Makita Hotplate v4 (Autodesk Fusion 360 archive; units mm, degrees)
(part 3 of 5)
sketch "Plan" plane through (0, 0, 0) normal (0, 0, 1) x axis (1, 0, 0)
  line L1 (-35, -5) -> (35, -5)
  line L2 (-35, 5) -> (-35, -5)
  line L3 (35, 5) -> (-35, 5)
  line L4 (35, -5) -> (35, 5)
  line L5 (-32.4254, -7.4282) -> (-37.6216, -10.4282)
  line L6 (-40.4254, 6.4282) -> (-32.4254, -7.4282)
  line L7 (-45.6216, 3.4282) -> (-40.4254, 6.4282)
  line L8 (-37.6216, -10.4282) -> (-45.6216, 3.4282)
  line L9 (-35.0235, -8.9282) -> (-43.0235, 4.9282)
  line L10 (-35, -3.8) -> (-35.5, -3.8)
  line L11 (-35, 3.8) -> (-35.5, 3.8)
  line L12 (-35.5, -3.8) -> (-35.5, 3.8)
  line L13 (-35.5, 0) -> (-35, 0)
  line L14 (0, -5) -> (0, 5)
  line L15 (35, 0) -> (-35, 0)
  line L16 (-30.35, 3) -> (-35, 3)
  line L17 (-30.35, -5) -> (-30.35, 3)
  line L18 (-58.5, 1.7343) -> (-50.3233, -12.4282)
  line L19 (-58.5, 20.45) -> (-58.5, 1.7343)
  line L20 (-35.1895, 7.2) -> (0, 7.2)
  line L21 (-33.6575, -9.2942) -> (-41.1827, 3.7398)
  line L22 (35, 20.45) -> (0, 20.45)
  line L23 (35, 7.2) -> (0, 7.2)
  line L24 (-58.5, 20.45) -> (0, 20.45)
  line L25 (0, 20.45) -> (0, 7.2)
  line L26 (-35.1895, 7.2) -> (-41.1827, 3.7398)
  line L27 (-35, 7.2) -> (-35.1895, 7.2)
  line L28 (-35, 20.45) -> (-35, 7.2)
  line L29 (35, 20.45) -> (35, 7.2)
  line L30 (-39.0857, -12.4282) -> (-33.6575, -9.2942)
  line L31 (-50.3233, -12.4282) -> (-39.0857, -12.4282)
  line L32 (40.7735, -5) -> (35, 5)
  line L33 (7.5981, -1.5) -> (5, 0)
  line L34 (49, 20.45) -> (35, 20.45)
  arc A1 centre (-32.1029, 0) radius 5.0971 clockwise from (-35.5, -3.8) to (-35.5, 3.8)
  circle C1 centre (-33.25, 0) radius 3
  circle C2 centre (5, 0) radius 3
  circle C3 centre (-33.35, 0) radius 3
  point P10 (-43.0235, 4.9282)
  point P11 (-35.0235, -8.9282)
  point P15 (-35, -3.8)
  point P16 (-35, 3.8)
  point P14 (-35.5, -3.8)
  point P17 (-35.5, -3.8)
  point P18 (-35, 0)
  point P19 (-35.5, 0)
  point P20 (-37.2, 0)
  point P21 (0, 5)
  point P22 (0, -5)
  point P1 (0, 0)
  point P24 (35, 0)
  point P23 (-33.25, 0)
  point P25 (-35, 3)
  point P27 (-30.35, -5)
  point P28 (-39.0235, -2)
  point P33 (0, 7.2)
  point P36 (0, 7.2)
  point P30 (-58.5, 20.45)
  point P38 (-58.5, 20.45)
  point P31 (-35.1895, 7.2)
  point P39 (-35.1895, 7.2)
  point P41 (-35, 20.45)
  point P4 (-35, 5)
  point P42 (35, 7.2)
  point P5 (35, 5)
  point P37 (35, 7.2)
  point P47 (40.7735, -5)
  point P48 (41.1575, -5.6651)
  point P35 (5, 0)
  point P49 (5, 0)
  point P50 (7.5981, -1.5)
  point P51 (7.5981, -1.5)
  point P53 (-33.35, 0)
  point P3 (-35, -5)
  point P6 (-37.6216, -10.4282)
  point P9 (-45.6216, 3.4282)
  point P8 (-40.4254, 6.4282)
  point P13 (-35.5, 3.8)
  point P34 (0, 20.45)
  point P43 (35, 20.45)
  point P52 (49, 20.45)
  horizontal L1
  vertical L2
  horizontal L3
  vertical L4
  perpendicular L5 L6
  parallel L5 L7
  parallel L6 L8
  midpoint L7 P10
  midpoint L5 P11
  coincident L2 P15
  perpendicular L2 L10
  coincident L2 P16
  perpendicular L2 L11
  perpendicular L11 L12
  coincident P14 P17
  midpoint L2 P18
  perpendicular L2 L13
  midpoint L12 P19
  midpoint A1 P20
  midpoint L3 P21
  midpoint L1 P22
  midpoint P1 L14
  midpoint L4 P24
  coincident P23 L15
  coincident L2 P25
  perpendicular L2 L16
  coincident L1 P27
  perpendicular L1 L17
  midpoint L9 P28
  vertical L19
  horizontal L20
  coincident P33 P36
  coincident P30 P38
  perpendicular L22 L25
  coincident P1 L25
  horizontal L22
  horizontal L23
  horizontal L24
  perpendicular L6 L26
  coincident P31 P39
  parallel L9 L21
  parallel L9 L18
  parallel L20 L27
  coincident L24 P41
  perpendicular L24 L28
  coincident P4 L28
  coincident L23 P42
  perpendicular L22 L29
  coincident P5 L29
  tangent L6 C1
  perpendicular L21 L30
  coincident P37 P42
  coincident L1 P47
  horizontal L31
  parallel L9 L32
  coincident L32 P48
  coincident P35 P49
  coincident C2 P50
  coincident P50 P51
  equal C1 C2
  coincident L15 P35
  perpendicular L29 L34
  coincident L15 P53
  equal C1 C3
  dimension "d1706" distance P3 P4 = 10
  dimension "d1707" distance P6 P9 = 16
  dimension "d1708" distance P8 P9 = 6
  dimension "d1709" distance P13 P17 = 7.6
  dimension "d1710" distance L2 P20 = 2.2
  dimension "d1711" distance P13 P16 = 0.5
  dimension "d1712" distance P1 L2 = 35
  dimension "d1713" diameter C1 = 6
  dimension "d1714" distance L2 P23 = 1.75
  dimension "d1715" distance P23 L17 = 2.9 (= "d1713 / 2 - d2773")
  dimension "d1716" distance P23 L16 = 3 (= "d1713 / 2")
  dimension "d1717" angle L2 L9 = 30
  dimension "d1723" distance L15 P28 = 2
  dimension "d1734" distance P28 L21 = 1
  dimension "d1740" distance L2 L19 = 23.5
  dimension "d1955" distance L15 L20 = 7.2
  dimension "d1988" distance P33 P34 = 13.25
  dimension "d1989" distance P4 L26 = 2
  dimension "d1990" distance P28 L18 = 15
  dimension "d2127" distance L3 L20 = 2.2
  dimension "d2158" distance L19 L28 = 23.5
  dimension "d2277" distance P6 L30 = 1
  dimension "d2278" distance P6 L31 = 2
  dimension "d2412" angle L15 L33 = 30
  dimension "d2460" distance P35 L29 = 30 (= "right_int_offset")
  dimension "d2467" distance P43 P52 = 14
  dimension "d2773" distance P23 P53 = 0.1
  dimension "d523" OffsetX = 0
  dimension "d524" OffsetY = 0
  dimension "d525" OffsetZ = 0
  dimension "d526" AngleZ = 0
  dimension "d567" OffsetX = 0
  dimension "d568" OffsetY = 0
  dimension "d569" OffsetZ = 0
  dimension "d570" AngleZ = 0
  dimension "d2536" distance = 15.5
  dimension "d2537" radius = 29.5
  dimension "d2538" radius = 29
  dimension "d2539" distance = 8
  dimension "d2540" distance = 12
  dimension "d2542" distance = 30
  dimension "d2543" radius = 45
  dimension "d2544" Side1Offset = 0.5
  dimension "d2545" TaperAngle = 0
  dimension "d2546" Side1Offset = 0
  dimension "d2547" TaperAngle = 0
  dimension "d2548" AlongDistance = -8
  dimension "d2549" TaperAngle = 0
  dimension "d2550" Side1Offset = 0
  dimension "d2551" TaperAngle = 0
  dimension "d2552" angle = 8
  dimension "d2553" distance = 39
  dimension "d2554" Side1Offset = 0
  dimension "d2555" TaperAngle = 0
  dimension "d2556" distance = 0.5
  dimension "d2558" Radius = 4
  dimension "d2560" Radius = 3
  dimension "d2562" Radius = 5
  dimension "d2564" Radius = 2
  dimension "d2566" Radius = 12
  dimension "d2568" Radius = 2
  dimension "d2569" Distance = 2
  dimension "d2570" Distance = 2
  dimension "d2571" Distance = 4
  dimension "d2573" Side1Offset = 0
  dimension "d2574" TaperAngle = 0
  dimension "d2575" Side1Offset = 0
  dimension "d2576" TaperAngle = 0
  dimension "d2577" distance = -0.25
  dimension "d2579" Radius = 6
  dimension "d2581" ChordLen = 1
  dimension "d2583" ChordLen = 1
  dimension "d2585" ChordLen = 1
  dimension "d2587" ChordLen = 1
  dimension "d2588" distance = 12
  dimension "d2589" diameter = 6
  dimension "d2590" diameter = 3.25
  dimension "d2591" distance = 5.5
  dimension "d2592" angle = 90
  dimension "d2593" distance = 5.4
  dimension "d2594" Side1Offset = 0
  dimension "d2595" TaperAngle = 0
  dimension "d2596" AlongDistance = -4.5
  dimension "d2597" TaperAngle = 0
  dimension "d2598" Distance = 0.5
  dimension "d2599" Distance = 1.5
  dimension "d2600" distance = 25
  dimension "d2602" TotalAngle = 360
  dimension "d2603" distance = 5.5
  dimension "d2604" diameter = 6
  dimension "d2605" diameter = 3.25
  dimension "d2607" distance = 3.75
  dimension "d2608" distance = 1.5
  dimension "d2609" Side1Offset = 0
  dimension "d2610" TaperAngle = 0
  dimension "d2611" AlongDistance = -4.5
  dimension "d2612" TaperAngle = 0
  dimension "d2613" Distance = 0.5
  dimension "d2614" Distance = 1.5
  dimension "d2615" countU = 11
  dimension "d2616" TotalAngle = 360
  dimension "d1941" Side1Offset = 0
  dimension "d1942" TaperAngle = 0
  dimension "d1943" Side1Offset = 0
  dimension "d1944" TaperAngle = 0
  dimension "d1947" alignAngle = 0
  dimension "d1948" alignOffsetX = 0
  dimension "d1949" alignOffsetY = 0
  dimension "d1950" alignOffsetZ = 0
  dimension "d1951" alignAngle = 90
  dimension "d1952" alignOffsetX = 0
  dimension "d1953" alignOffsetY = 0
  dimension "d1954" alignOffsetZ = 0
  dimension "d1958" ProfileOffset = 0
  dimension "d1959" Side1Offset = 0
  dimension "d1960" TaperAngle = 0
  dimension "d1961" distance = -0.075
  dimension "d1962" ProfileOffset = 0
  dimension "d1963" Side1Offset = 0
  dimension "d1964" TaperAngle = 0
  dimension "d1965" distance = -0.075
  dimension "d1966" distance = 67
  dimension "d1967" distance = 33
  dimension "d1968" diameter = 2.5
  dimension "d1969" distance = 4
  dimension "d1970" distance = 29
  dimension "d1971" distance = 34
  dimension "d1972" distance = 54
  dimension "d1973" distance = 4
  dimension "d1974" distance = 3
  dimension "d1975" distance = 3
  dimension "d1976" distance = 5
  dimension "d1977" distance = 5
  dimension "d1978" distance = 1
  dimension "d1979" distance = 1
  dimension "d1980" distance = 10
  dimension "d1981" distance = 10
  dimension "d1982" distance = 6
  dimension "d1983" ProfileOffset = 0
  dimension "d1984" Side1Offset = 0
  dimension "d1985" TaperAngle = 0
  dimension "d1987" Radius = 1.05 (= "od_mintool / 2")
  dimension "d1597" distance = 1.6
  dimension "d1598" distance = 67
  dimension "d1599" diameter = 4.25
  dimension "d1600" diameter = 3.3
  dimension "d1601" distance = 1
  dimension "d1602" distance = 1
  dimension "d1603" distance = 0.5
  dimension "d1604" distance = 12
  dimension "d1605" distance = 0.25
  dimension "d1606" distance = 0.25
  dimension "d1607" distance = 1
  dimension "d1608" distance = 8
  dimension "d1609" distance = 4.5
  dimension "d1610" distance = 4.5
  dimension "d1612" TaperAngle = 0
  dimension "d1613" AlongDistance = -53 (= "-20 mm - 33 mm")
  dimension "d1614" TaperAngle = 0
  dimension "d1615" ProfileOffset = 0.1
  dimension "d1616" Side1Offset = 0
  dimension "d1617" TaperAngle = 0
  dimension "d1618" leftDistance = 1
  dimension "d1619" distance = 67
  dimension "d1620" distance = 33
  dimension "d1621" distance = 0.5
  dimension "d1622" distance = 24.5
  dimension "d1623" diameter = 2.5
  dimension "d1624" distance = 4
  dimension "d1625" distance = 34
  dimension "d1626" distance = 54
  dimension "d1627" distance = 4
  dimension "d1628" distance = 29
  dimension "d1631" distance = 1
  dimension "d1633" distance = 3
  dimension "d1634" distance = 2.44 (= "d1643")
  dimension "d1635" diameter = 4
  dimension "d1636" distance = 15
  dimension "d1637" distance = 3
  dimension "d1638" distance = 15
  dimension "d1639" distance = 2
  dimension "d1640" Side1Offset = 0
  dimension "d1641" TaperAngle = 0
  dimension "d1642" distance = 2.44
  dimension "d1643" distance = 2.44
  dimension "d1644" AlongDistance = -16
  dimension "d1645" TaperAngle = 0
  dimension "d1647" Radius = 1
  dimension "d1649" Radius = 1
  dimension "d1651" Radius = 5
  dimension "d1653" Radius = 1
  dimension "d1654" diameter = 12
  dimension "d1655" Side1Offset = 0
  dimension "d1656" TaperAngle = 0
  dimension "d1658" Radius = 2
  dimension "d1659" distance = 20
  dimension "d1660" distance = 5
  dimension "d1661" distance = 5
  dimension "d981" distance = 15 (= "( 30 / 2 ) * 1 mm")
  dimension "d982" distance = 8
  dimension "d983" distance = 1.5
  dimension "d984" distance = 0.3
  dimension "d985" distance = 4
  dimension "d987" distance = 1
  dimension "d988" distance = 7.5
  dimension "d989" distance = 5
  dimension "d990" distance = 0.5
  dimension "d991" AlongAngle = 60
  dimension "d992" AgainstAngle = 60
  dimension "d993" distance = 4
  dimension "d994" angle = 60
  dimension "d995" angle = 60 (= "d994")
  dimension "d1004" diameter = 6.5
  dimension "d1005" distance = 1.5
  dimension "d1006" AlongDistance = -10
  dimension "d1007" TaperAngle = 0
  dimension "d1008" Side1Offset = 0
  dimension "d1009" TaperAngle = 0
  dimension "d1010" ProfileOffset = 0
  dimension "d1011" AlongDistance = -0.5
  dimension "d1012" TaperAngle = 0
  dimension "d1013" AlongDistance = 2.5
  dimension "d1014" TaperAngle = 0
  dimension "d1015" leftDistance = 0.25
  dimension "d1017" Radius = 1
  dimension "d1019" TotalAngle = 360
  dimension "d1020" ProfileOffset = 0
  dimension "d1021" Side1Offset = 0
  dimension "d1022" TaperAngle = 0
  dimension "d1028" angle = 25
  dimension "d1029" ProfileOffset = 0
  dimension "d1030" Side1Offset = 0
  dimension "d1031" TaperAngle = 0
  dimension "d1032" ProfileOffset = 0
  dimension "d1034" TaperAngle = 0
  dimension "d1035" Side1Offset = 0
  dimension "d1036" distance = 3
  dimension "d1037" leftDistance = 3
  dimension "d1038" rightDistance = 17.25
  dimension "d1039" Side1Offset = 0
  dimension "d1040" TaperAngle = 0
  dimension "d1042" TotalAngle = 360
  dimension "d1043" Side1Offset = 0
  dimension "d1044" TaperAngle = 2
  dimension "d1045" angle = 1
  dimension "d1047" Side1Offset = 0
  dimension "d1048" TaperAngle = 0
  dimension "d1049" distance = -1 (= "0 mm - 1 mm")
  dimension "d1051" TotalAngle = 360
  dimension "d1053" angle = 43.731
  dimension "d1054" angle = 28 (= "d1055 - d1056")
  dimension "d1055" angle = 50 (= "d1028 * 2")
  dimension "d1056" angle = 22
  dimension "d1058" Radius = 2
  dimension "d1060" Radius = 2
  dimension "d1061" alignAngle = 0
  dimension "d1062" alignOffsetX = 0
  dimension "d1063" alignOffsetY = 0
  dimension "d1064" alignOffsetZ = 0
  dimension "d1082" distance = 0.8
  dimension "d1084" distance = 0.8
  dimension "d1085" distance = 1.2
  dimension "d1086" distance = 1.2
  dimension "d1087" distance = 0.1
  dimension "d1093" Radius = 0.5
  dimension "d1095" Radius = 0.5
  dimension "d1097" Radius = 2
  dimension "d1103" distance = 1.3
  dimension "d1105" TotalAngle = 360
  dimension "d1106" distance = 2.75 (= "hw_m3hex_d / 2")
  dimension "d1107" distance = 1.75 (= "hw_m3_thru / 2")
  dimension "d1108" angle = 45
  dimension "d1109" distance = 3.6
  dimension "d1110" distance = 20
  dimension "d1111" distance = 1.7
  dimension "d1112" AlongAngle = 360
  dimension "d1113" Side1Offset = 0
  dimension "d1114" TaperAngle = 0
  dimension "d1116" TotalAngle = 360
  dimension "d1118" Radius = 2
  dimension "d1120" distance = 3.175 (= "1 / 8 * 1")
  dimension "d1121" radius = 12
  dimension "d1123" radius = 6.5
  dimension "d1124" angle = 60
  dimension "d1126" distance = 2.8797 (= "13 / 64 * 1  / 2 + 0.3 mm")
  dimension "d1127" distance = 9.5563 (= "7 / 32 * 1  + 4 mm")
  dimension "d1128" AlongDistance = -6
  dimension "d1129" diameter = 3.475 (= "1 / 8 * 1  + 0.3 mm")
  dimension "d1130" diameter = 1.7875 (= "1 / 16 * 1  + 0.2 mm")
  dimension "d1141" TwistAngle = 0
  dimension "d1142" TaperAngle = 0
  dimension "d1143" angle = 51
  dimension "d1144" distance = 2.8797 (= "d1126")
  dimension "d1145" diameter = 1.7875 (= "1 / 16 * 1  + 0.2 mm")
  dimension "d1150" TwistAngle = 0
  dimension "d1151" TaperAngle = 0
  dimension "d1152" distance = 1.7875 (= "1 / 16 * 1  + 0.2 mm")
  dimension "d1153" Side1Offset = 0
  dimension "d1154" TaperAngle = 0
  dimension "d1155" AlongDistance = -4
  dimension "d1156" TaperAngle = 0
  dimension "d1157" diameter = 5.3594 (= "13 / 64 * 1  + 0.2 mm")
  dimension "d1158" AlongDistance = 1.5
  dimension "d1159" TaperAngle = 0
  dimension "d1164" TwistAngle = 0
  dimension "d1165" TaperAngle = 0
  dimension "d1167" mirrorStitchTolerance = 0.1
  dimension "d1169" Radius = 0.4
  dimension "d1170" distance = 11
  dimension "d1171" distance = 1.0938 (= "( 1 / 16 * 1  + 0.2 mm ) / 2 + 0.2 mm")
  dimension "d1172" distance = 1.7
  dimension "d1173" distance = 1.7
  dimension "d1174" Side1Offset = 0
  dimension "d1175" TaperAngle = 0
  dimension "d1176" Side2Offset = -1
  dimension "d1177" Side2TaperAngle = 0
  dimension "d1179" mirrorStitchTolerance = 0.1
  dimension "d1181" Radius = 0.5
  dimension "d1182" alignAngle = 0
  dimension "d1183" alignOffsetX = 0
  dimension "d1184" alignOffsetY = 0
  dimension "d1185" alignOffsetZ = 0
  dimension "d1186" leftDistance = 0.75
  dimension "d1187" rightDistance = 3
  dimension "d1189" Radius = 12
  dimension "d1191" Radius = 2
  dimension "d1193" Radius = 0.5
  dimension "d1195" Radius = 0.5
  dimension "d1197" Radius = 0.5
  dimension "d1198" alignAngle = 0
  dimension "d1199" alignOffsetX = 0
  dimension "d1200" alignOffsetY = 0
  dimension "d1201" alignOffsetZ = 0
  dimension "d1202" distance = 13.5
sketch "Elevation" plane through (0, 0, 0) normal (0, 1, 0) x axis (1, 0, 0)
  line L1 (35, 0) -> (-35, 0)
  line L2 (35, -120) -> (35, 0)
  line L3 (-35, -120) -> (35, -120)
  line L4 (-35, 0) -> (-35, -120)
  line L5 (-35, 0) -> (35, 0)
  line L6 (25, -108) -> (-25, -108)
  line L7 (25, -12) -> (25, -108)
  line L8 (-25, -12) -> (25, -12)
  line L9 (-25, -108) -> (-25, -12)
  line L10 (-38, -80.5) -> (-58.5, -80.5)
  line L11 (-38, -39.5) -> (-38, -80.5)
  line L12 (-58.5, -39.5) -> (-38, -39.5)
  line L13 (-43.25, -84.75) -> (-53.25, -84.75)
  line L14 (-43.25, -35.25) -> (-43.25, -84.75)
  line L15 (-53.25, -35.25) -> (-43.25, -35.25)
  line L16 (-53.25, -84.75) -> (-53.25, -35.25)
  line L17 (-48.25, -60) -> (-48.25, -84.75)
  line L18 (-38, -60) -> (-48.25, -60)
  line L19 (-58.5, -90) -> (-58.5, -80.5)
  line L20 (-35, -90) -> (-58.5, -90)
  line L21 (-58.5, -30) -> (-35, -30)
  line L22 (-58.5, -39.5) -> (-58.5, -30)
  line L23 (-50.0746, -84.75) -> (-51.6623, -87.5)
  line L24 (-51.6623, -82) -> (-50.0746, -84.75)
  line L25 (-54.8377, -82) -> (-51.6623, -82)
  line L26 (-56.4254, -84.75) -> (-54.8377, -82)
  line L27 (-54.8377, -87.5) -> (-56.4254, -84.75)
  line L28 (-51.6623, -87.5) -> (-54.8377, -87.5)
  line L29 (-46.4254, -84.75) -> (-44.8377, -82)
  line L30 (-44.8377, -87.5) -> (-46.4254, -84.75)
  line L31 (-41.6623, -87.5) -> (-44.8377, -87.5)
  line L32 (-40.0746, -84.75) -> (-41.6623, -87.5)
  line L33 (-41.6623, -82) -> (-40.0746, -84.75)
  line L34 (-44.8377, -82) -> (-41.6623, -82)
  line L35 (-40.0746, -35.25) -> (-41.6623, -32.5)
  line L36 (-41.6623, -38) -> (-40.0746, -35.25)
  line L37 (-44.8377, -38) -> (-41.6623, -38)
  line L38 (-46.4254, -35.25) -> (-44.8377, -38)
  line L39 (-41.6623, -32.5) -> (-44.8377, -32.5)
  line L40 (-44.8377, -32.5) -> (-46.4254, -35.25)
  line L41 (-54.8377, -38) -> (-51.6623, -38)
  line L42 (-56.4254, -35.25) -> (-54.8377, -38)
  line L43 (-54.8377, -32.5) -> (-56.4254, -35.25)
  line L44 (-51.6623, -32.5) -> (-54.8377, -32.5)
  line L45 (-51.6623, -38) -> (-50.0746, -35.25)
  line L46 (-50.0746, -35.25) -> (-51.6623, -32.5)
  line L47 (-49.25, -85.75) -> (-49.25, -80.5)
  line L48 (-47.25, -80.5) -> (-47.25, -85.75)
  line L49 (-48.25, -85.75) -> (-48.25, -80.5)
  line L50 (-49.25, -34.25) -> (-49.25, -39.5)
  line L51 (-47.25, -39.5) -> (-47.25, -34.25)
  line L52 (-38, -90) -> (-38, -80.5)
  line L53 (-38, -30) -> (-38, -39.5)
  line L54 (35, -54) -> (-35, -54)
  line L55 (0, 0) -> (0, -120)
  line L56 (25, -64.25) -> (35, -64.25)
  line L57 (25, -43.75) -> (35, -43.75)
  line L58 (25, -28.75) -> (35, -28.75)
  line L59 (25, -79.25) -> (35, -79.25)
  line L60 (30, -64.25) -> (30, -43.75)
  line L61 (5, -120) -> (5, 0)
  line L62 (2.2, -39) -> (2.2, -68)
  line L63 (8.2, -63) -> (2.2, -63)
  line L64 (8.2, -68) -> (8.2, -63)
  line L65 (8.2, -39) -> (8.2, -63)
  line L66 (9.25, -20) -> (0.75, -20)
  line L67 (9.25, -37) -> (9.25, -20)
  line L68 (0.75, -37) -> (9.25, -37)
  line L69 (0.75, -20) -> (0.75, -37)
  line L70 (-30.35, -97) -> (-35, -97)
  line L71 (-30.35, -120) -> (-30.35, -97)
  line L72 (-30.35, -97) -> (-30.35, 0)
  line L73 (-35, -114) -> (-30.35, -114)
  line L74 (8.2, -46) -> (2.2, -46)
  line L75 (-37.35, -114) -> (-35, -114)
  line L76 (-37.35, -120) -> (-37.35, -114)
  line L77 (-35, -120) -> (-37.35, -120)
  line L78 (5.5, -46) -> (5.5, -63)
  line L79 (-15, -7.55) -> (-35, -7.55)
  line L80 (-15, -16.45) -> (-35, -16.45)
  line L81 (45, -120) -> (35, -120)
  line L82 (45, 0) -> (45, -120)
  line L83 (35, 0) -> (45, 0)
  line L84 (-27.5, -96.75) -> (-35, -96.75)
  line L85 (-27.5, -23.25) -> (-27.5, -96.75)
  line L86 (-35, -23.25) -> (-27.5, -23.25)
  line L87 (2.2, -68) -> (20, -68)
  line L88 (20, -39) -> (2.2, -39)
  line L89 (20, -39) -> (20, -68)
  line L90 (-36.6, -23.25) -> (-35, -23.25)
  line L91 (-36.6, 0) -> (-36.6, -23.25)
  line L92 (-35, 0) -> (-36.6, 0)
  circle C1 centre (-53.25, -84.75) radius 1.625
  circle C2 centre (-43.25, -84.75) radius 1.625
  circle C3 centre (-43.25, -35.25) radius 1.625
  circle C4 centre (-53.25, -35.25) radius 1.625
  arc A1 centre (-48.25, -85.75) radius 1 clockwise from (-47.25, -85.75) to (-49.25, -85.75)
  arc A2 centre (-48.25, -80.5) radius 1 clockwise from (-49.25, -80.5) to (-47.25, -80.5)
  arc A3 centre (-48.25, -34.25) radius 1 clockwise from (-49.25, -34.25) to (-47.25, -34.25)
  arc A4 centre (-48.25, -39.5) radius 1 clockwise from (-47.25, -39.5) to (-49.25, -39.5)
  circle C5 centre (-29, -12) radius 1.65
  circle C6 centre (-29, -12) radius 4
  circle C7 centre (-25, -108) radius 1.65
  circle C8 centre (-25, -108) radius 4
  circle C9 centre (40.5, -54) radius 1.65
  circle C10 centre (40.5, -54) radius 4
  circle C11 centre (20, -53.5) radius 13.3
  arc A5 centre (20, -53.5) radius 14.5 clockwise from (20, -39) to (20, -68)
  point P2 (-35, 0)
  point P4 (-35, 0)
  point P3 (35, 0)
  point P1 (0, 0)
  point P15 (0, 0)
  point P24 (-48.25, -84.75)
  point P27 (-43.25, -60)
  point P26 (-38, -60)
  point P28 (-48.25, -80.5)
  point P30 (-35, -90)
  point P19 (-58.5, -39.5)
  point P32 (-58.5, -39.5)
  point P20 (-53.25, -84.75)
  point P33 (-53.25, -84.75)
  point P21 (-43.25, -84.75)
  point P34 (-43.25, -84.75)
  point P41 (-53.25, -84.75)
  point P48 (-43.25, -84.75)
  point P35 (-51.6623, -87.5)
  point P60 (-51.6623, -32.5)
  point P36 (-50.0746, -84.75)
  point P61 (-50.0746, -35.25)
  point P37 (-51.6623, -82)
  point P56 (-51.6623, -38)
  point P38 (-54.8377, -82)
  point P57 (-54.8377, -38)
  point P39 (-56.4254, -84.75)
  point P58 (-56.4254, -35.25)
  point P40 (-54.8377, -87.5)
  point P59 (-54.8377, -32.5)
  point P42 (-44.8377, -82)
  point P53 (-44.8377, -38)
  point P43 (-46.4254, -84.75)
  point P54 (-46.4254, -35.25)
  point P44 (-44.8377, -87.5)
  point P55 (-44.8377, -32.5)
  point P45 (-41.6623, -87.5)
  point P50 (-41.6623, -32.5)
  point P46 (-40.0746, -84.75)
  point P51 (-40.0746, -35.25)
  point P47 (-41.6623, -82)
  point P52 (-41.6623, -38)
  point P68 (-48.25, -85.75)
  point P67 (-48.25, -80.5)
  point P63 (-49.25, -80.5)
  point P69 (-49.25, -39.5)
  point P64 (-49.25, -85.75)
  point P70 (-49.25, -34.25)
  point P65 (-47.25, -85.75)
  point P72 (-47.25, -34.25)
  point P66 (-47.25, -80.5)
  point P73 (-47.25, -39.5)
  point P75 (-38, -90)
  point P76 (-38, -30)
  point P77 (-35, -54)
  point P78 (35, -54)
  point P8 (-35, -30)
  point P79 (0, -120)
  point P80 (0, 0)
  point P81 (0, -108)
  point P83 (-58.5, 0)
  point P84 (35, -64.25)
  point P85 (25, -64.25)
  point P86 (35, -43.75)
  point P87 (25, -43.75)
  point P88 (35, -28.75)
  point P89 (25, -28.75)
  point P90 (35, -79.25)
  point P91 (25, -79.25)
  point P92 (30, -43.75)
  point P93 (30, -64.25)
  point P94 (30, -54)
  point P95 (5, 0)
  point P96 (5, 0)
  point P97 (5, -120)
  point P100 (2, -54)
  point P101 (2.2, -63)
  point P104 (8.2, -39)
  point P109 (5, -20)
  point P110 (-35, -97)
  point P112 (-30.35, -120)
  point P113 (-30.35, 0)
  point P114 (-30.35, 0)
  point P115 (-30.35, -114)
  point P116 (-35, -114)
  point P117 (2.2, -46)
  point P118 (8.2, -46)
  point P7 (-35, -120)
  point P121 (-35, -120)
  point P122 (5.5, -63)
  point P123 (5.5, -46)
  point P126 (-35, -7.55)
  point P128 (-35, -16.45)
  point P124 (-29, -12)
  point P130 (-25, -108)
  point P134 (5, -54)
  point P5 (35, 0)
  point P137 (35, 0)
  point P138 (-35, -96.75)
  point P141 (-35, -23.25)
  point P142 (-27.5, -60)
  point P143 (20, -53.5)
  point P144 (20, -53.5)
  point P103 (8.2, -68)
  point P132 (40.5, -54)
  point P149 (-35, 0)
  point P6 (35, -120)
  point P16 (-58.5, -80.5)
  point P17 (-38, -80.5)
  point P18 (-38, -39.5)
  point P23 (-53.25, -35.25)
  point P11 (-25, -108)
  point P12 (25, -108)
  point P13 (25, -12)
  point P102 (8.2, -63)
  point P105 (0.75, -20)
  point P106 (9.25, -20)
  point P108 (0.75, -37)
  point P111 (-30.35, -97)
  point P119 (-37.35, -114)
  point P14 (-25, -12)
  point P127 (-15, -7.55)
  point P125 (-29, -12)
  point P131 (-25, -108)
  point P135 (45, -120)
  point P133 (40.5, -54)
  point P140 (-27.5, -23.25)
  point P139 (-27.5, -96.75)
  point P148 (-36.6, 0)
  horizontal L1
  vertical L2
  horizontal L3
  vertical L4
  coincident P2 P4
  coincident P3 L2
  horizontal L6
  vertical L7
  horizontal L8
  vertical L9
  coincident P1 P15
  horizontal L10
  perpendicular L10 L11
  perpendicular L11 L12
  horizontal L13
  vertical L14
  horizontal L15
  vertical L16
  midpoint L13 P24
  perpendicular L10 L17
  perpendicular L17 L18
  midpoint L14 P27
  coincident L18 P27
  midpoint L11 P26
  midpoint L10 P28
  coincident L17 P28
  perpendicular L10 L19
  coincident L4 P30
  perpendicular L4 L20
  perpendicular L4 L21
  perpendicular L21 L22
  coincident P19 P32
  coincident L19 P32
  equal L19 L22
  coincident P20 P33
  coincident P21 P34
  equal C1 C2
  coincident P33 P41
  horizontal L28
  coincident P34 P48
  horizontal L31
  equal L28 L31
  symmetric L18 C1 C4
  symmetric L18 C2 C3
  symmetric L18 P35 P60
  symmetric L18 P36 P61
  symmetric L18 P37 P56
  symmetric L18 P38 P57
  symmetric L18 P39 P58
  symmetric L18 P40 P59
  symmetric L18 P42 P53
  symmetric L18 P43 P54
  symmetric L18 P44 P55
  symmetric L18 P45 P50
  symmetric L18 P46 P51
  symmetric L18 P47 P52
  tangent L47 A1
  tangent A1 L48
  parallel L47 L48
  tangent L48 A2
  tangent L47 A2
  coincident L17 P68
  perpendicular L10 L49
  coincident P28 P67
  symmetric L18 P63 P69
  symmetric L18 P64 P70
  symmetric L18 P65 P72
  symmetric L18 P66 P73
  symmetric L18 A1 A3
  symmetric L18 A2 A4
  coincident L20 P75
  perpendicular L20 L52
  coincident L21 P76
  perpendicular L21 L53
  coincident L4 P77
  coincident L2 P78
  perpendicular L2 L54
  coincident L4 P8
  midpoint L3 P79
  coincident P1 P80
  midpoint L6 P81
  coincident L55 P81
  coincident L19 P83
  coincident L2 P84
  coincident L7 P85
  perpendicular L7 L56
  coincident L2 P86
  coincident L7 P87
  perpendicular L7 L57
  coincident L2 P88
  coincident L7 P89
  perpendicular L7 L58
  coincident L2 P90
  coincident L7 P91
  perpendicular L7 L59
  midpoint L57 P92
  midpoint L56 P93
  midpoint L60 P94
  coincident L54 P94
  coincident P95 P96
  coincident L3 P97
  perpendicular L3 L61
  perpendicular L54 L62
  perpendicular L2 L88
  coincident L54 P100
  coincident L62 P101
  perpendicular L62 L63
  coincident P104 L88
  perpendicular L65 L88
  horizontal L66
  vertical L67
  horizontal L68
  vertical L69
  midpoint L66 P109
  coincident L61 P109
  coincident L4 P110
  perpendicular L4 L70
  coincident L3 P112
  perpendicular L3 L71
  coincident P113 P114
  vertical L72
  coincident L71 P115
  coincident L4 P116
  perpendicular L4 L73
  coincident L62 P117
  coincident L65 P118
  perpendicular L65 L74
  perpendicular L4 L75
  perpendicular L73 L76
  perpendicular L4 L77
  coincident P7 P121
  coincident L63 P122
  coincident L74 P123
  perpendicular L74 L78
  concentric C5 C6
  coincident L4 P126
  perpendicular L4 L79
  coincident L4 P128
  perpendicular L9 L80
  equal L79 L80
  coincident L8 P124
  concentric C7 C8
  coincident L6 P130
  concentric C9 C10
  coincident L61 P134
  coincident L54 P134
  perpendicular L2 L81
  perpendicular L3 L82
  perpendicular L2 L83
  coincident P5 P137
  coincident L4 P138
  perpendicular L72 L84
  perpendicular L84 L85
  coincident L4 P141
  perpendicular L4 L86
  midpoint L85 P142
  coincident P143 P144
  perpendicular L88 L89
  coincident P144 L89
  coincident P103 L87
  vertical L64
  horizontal L87
  coincident L54 P132
  perpendicular L4 L90
  perpendicular L90 L91
  perpendicular L91 L92
  coincident P4 P149
  dimension "d1741" distance P5 P6 = 120
  dimension "d2014" distance P16 P17 = 20.5
  dimension "d2015" distance P17 P18 = 41
  dimension "d2016" distance P20 P23 = 49.5
  dimension "d2017" distance P20 P21 = 10
  dimension "d2019" diameter C1 = 3.25
  dimension "d2020" distance P38 L28 = 5.5
  dimension "d2021" distance P64 L48 = 2
  dimension "d2204" distance L13 P68 = 1
  dimension "d2269" distance P4 L18 = 60
  dimension "d2271" distance P11 P12 = 50
  dimension "d2272" distance P12 P13 = 96
  dimension "d2273" distance P1 L8 = 12
  dimension "d2274" distance L3 L6 = 12 (= "d2273")
  dimension "d2275" distance P6 P7 = 70
  dimension "d2279" distance L20 P40 = 2.5
  dimension "d2295" distance P88 P90 = 50.5
  dimension "d2296" distance P84 P86 = 20.5
  dimension "d2297" distance L59 P93 = 15
  dimension "d2298" distance L58 P92 = 15 (= "d2297")
  dimension "d2336" distance P13 L54 = 42
  dimension "d2337" distance L6 L54 = 54
  dimension "d2618" distance L61 L62 = 2.8
  dimension "d2619" distance P101 P102 = 6
  dimension "d2620" distance P100 L63 = 9
  dimension "d2622" distance P105 P106 = 8.5
  dimension "d2623" distance P105 P108 = 17
  dimension "d2625" distance P112 L73 = 6
  dimension "d2626" distance P111 L73 = 17
  dimension "d2641" distance P100 L74 = 8
  dimension "d2643" distance P115 P119 = 7
  dimension "d2675" distance L61 L78 = 0.5
  dimension "d2676" diameter C5 = 3.3
  dimension "d2677" diameter C6 = 8
  dimension "d2678" distance P14 L79 = 4.45 (= "( 8.9 / 2 ) * 1 mm")
  dimension "d2679" distance P14 L80 = 4.45 (= "d2678")
  dimension "d2680" distance P126 P127 = 20
  dimension "d2681" distance L4 P125 = 6
  dimension "d2682" diameter C7 = 3.3
  dimension "d2683" diameter C8 = 8
  dimension "d2684" distance L4 P131 = 10
  dimension "d2693" diameter C9 = 3.3
  dimension "d2694" diameter C10 = 8
  dimension "d2695" distance P108 P117 = 9
  dimension "d2713" distance P6 P135 = 10
  dimension "d2714" distance P133 L82 = 4.5
  dimension "d2718" distance P140 P141 = 7.5
  dimension "d2719" distance P139 P140 = 73.5
  dimension "d2720" distance L1 P142 = 60
  dimension "d2757" distance L55 P143 = 20
  dimension "d2759" diameter C11 = 26.6
  dimension "d2760" radius A5 = 14.5 (= "( 29 / 2 ) * 1 mm")
  dimension "d2761" distance L54 P143 = 0.5
  dimension "d2772" distance P148 P149 = 1.6
  dimension "d1938" diameter = 4.25
  dimension "d1940" diameter = 8
  dimension "d1945" distance = 25
  dimension "d1946" distance = 30
  dimension "d1956" distance = 5 (= "t_sheet_THIN")
  dimension "d1957" distance = 5.5 (= "d1748")
extrude "Extrude245" sketch "Elevation" profile of L1 L2 L3 L4 L5 L87 L62 L88 L63 L64 L65 L66 L67 L68 L69 L70 L71 L73 L74 L75 L76 L77 L78 C5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 to an object
extrude "Extrude246" sketch "Elevation" profile of L4 L62 L63 L65 L70 L71 L73 L74 L78 to an object
fillet "Fillet116" ChordLen 3
sketch "Center Dowel Thru" plane through (0, 0, 63) normal (0, 0, -1) x axis (1, 0, 0)
  line L1 (5.5, -3) -> (5.2, -3)
  line L2 (8.2, 5) -> (8.2, -5)
  line L3 (2.2, 5) -> (8.2, 5)
  line L4 (2.2, 0) -> (2.2, 5)
  line L5 (5.2, 0) -> (2.2, 0)
  line L6 (5.2, -3) -> (5.2, 0)
  line L7 (5.5, -5) -> (5.5, -3)
  line L8 (8.2, -5) -> (5.5, -5)
  circle C1 centre (5.2, 0) radius 2.125
  arc A1 centre (5.2, 0) radius 3 clockwise from (5.2, -3) to (2.2, 0)
  circle C2 centre (5.2, 0) radius 1.75
  point P2 (2.2, 0)
  point P8 (2.2, 0)
  point P3 (5.2, -3)
  point P10 (5.2, -3)
  point P7 (5.2, 0)
  point P9 (5.2, 0)
  coincident P2 P8
  perpendicular L4 L5
  perpendicular L5 L6
  coincident P3 P10
  coincident P7 P9
  concentric A1 C2
  dimension "d2635" diameter C1 = 4.25
  dimension "d2638" diameter C2 = 3.5
extrude "Extrude247" cut sketch "Center Dowel Thru" profile of C1 C2 to an object
sketch "Upper Left Dowel Thru" plane through (0, 0, 114) normal (0, 0, -1) x axis (1, 0, 0)
  line L1 (-30.35, 5) -> (-30.35, 0)
  line L2 (-37.35, 5) -> (-30.35, 5)
  line L3 (-35, -3) -> (-35, -5)
  line L4 (-33.35, -3) -> (-35, -3)
  line L5 (-37.35, -5) -> (-37.35, 5)
  line L6 (-35, -5) -> (-37.35, -5)
  arc A1 centre (-33.35, 0) radius 3 clockwise from (-30.35, 0) to (-33.35, -3)
  circle C1 centre (-33.35, 0) radius 2.125
  concentric A1 C1
  dimension "d2642" diameter C1 = 4.25
extrude "Extrude249" cut sketch "Upper Left Dowel Thru" profile of C1 to an object
chamfer "Chamfer38" distance 0.5
sketch "Lower Left Contacts" plane through (-36.6, 0, 0) normal (-1, 0, 0) x axis (0, -1, 0)
  line L1 (-3, 97) -> (5, 97)
  line L2 (-3, 114) -> (-3, 97)
  line L3 (-5, 114) -> (-3, 114)
  line L4 (-5, 96.75) -> (-5, 114)
  line L5 (5, 97) -> (5, 96.75)
  line L6 (0, 6.2) -> (0, 17.8)
  line L7 (-2.5, 12) -> (5, 16.3301)
  line L8 (5, 7.6699) -> (-2.5, 12)
  line L9 (-2.5, 12) -> (0, 12)
  line L10 (5, 96.75) -> (-5, 96.75)
  line L11 (5, 96.75) -> (5, 97)
  line L12 (-5, 0) -> (-5, 23.25)
  line L13 (5, 0) -> (-5, 0)
  line L14 (5, 23.25) -> (5, 0)
  line L15 (-5, 23.25) -> (5, 23.25)
  line L16 (5, 12) -> (3.125, 15.2476)
  line L17 (-2.5, 12) -> (5, 12)
  circle C1 centre (0, 17.8) radius 1.8
  circle C2 centre (0, 6.2) radius 1.8
  circle C3 centre (0, 17.8) radius 4
  point P9 (0, 17.8)
  point P11 (0, 17.8)
  point P10 (0, 6.2)
  point P12 (0, 6.2)
  point P8 (0, 12)
  point P13 (5, 16.3301)
  point P15 (5, 7.6699)
  point P16 (0, 12)
  point P25 (5, 12)
  point P24 (3.125, 15.2476)
  coincident P9 P11
  coincident P10 P12
  vertical L6
  midpoint P8 L6
  equal C1 C2
  coincident L5 P13
  coincident L5 P15
  coincident P8 P16
  horizontal L9
  concentric C1 C3
  coincident L14 P25
  horizontal L17
  coincident L7 P24
  perpendicular L7 L16
  dimension "d2647" distance P11 P12 = 11.6
  dimension "d2648" diameter C1 = 3.6
  dimension "d2649" angle L7 L8 = 60 (= "d2650 * 2")
  dimension "d2650" angle L7 L9 = 30
  dimension "d2774" diameter C3 = 8
  dimension "d2777" distance P24 P25 = 3.75
extrude "Extrude250" cut sketch "Lower Left Contacts" profile of C1 C2 against normal blind 20
extrude "Extrude251" cut sketch "Lower Left Contacts" profile of L7 L8 L14 against normal blind 5
chamfer "Chamfer39" distance 5 distance 3.75
chamfer "Chamfer41" distance 3
fillet "Fillet117" ChordLen 4
chamfer "Chamfer42" distance 1
sketch "PCB Mount" plane through (-27.5, 0, 0) normal (-1, 0, 0) x axis (0, -1, 0)
  line L1 (-5, 23.25) -> (-5, 96.75)
  line L2 (5, 23.25) -> (-5, 23.25)
  line L3 (5, 96.75) -> (5, 23.25)
  line L4 (-5, 96.75) -> (5, 96.75)
  line L5 (3, 43.55) -> (3, 76.45)
  line L6 (5, 60) -> (3, 60)
  line L7 (3, 27.5) -> (3, 43.55)
  line L8 (3, 92.5) -> (3, 76.45)
  line L9 (41.3, 96.75) -> (5, 96.75)
  line L10 (41.3, 23.25) -> (41.3, 96.75)
  line L11 (5, 23.25) -> (41.3, 23.25)
  line L12 (-0.7, 96.75) -> (-0.7, 23.25)
  line L13 (37.3, 82.5) -> (37.3, 37.5)
  line L14 (37.3, 27.5) -> (3, 27.5)
  line L15 (37.3, 92.5) -> (3, 92.5)
  line L16 (6, 73.95) -> (-0.7, 73.95)
  line L17 (6, 46.05) -> (6, 73.95)
  line L18 (-0.7, 46.05) -> (6, 46.05)
  line L19 (31.8, 94.5) -> (18.3, 94.5)
  line L20 (31.8, 89.5) -> (31.8, 94.5)
  line L21 (18.3, 89.5) -> (31.8, 89.5)
  line L22 (18.3, 94.5) -> (18.3, 89.5)
  circle C1 centre (3, 76.45) radius 0.85
  circle C2 centre (3, 43.55) radius 0.85
  circle C3 centre (3, 92.5) radius 1.75
  circle C4 centre (3, 27.5) radius 1.75
  circle C5 centre (37.3, 82.5) radius 1.75
  circle C6 centre (37.3, 37.5) radius 1.75
  point P6 (3, 76.45)
  point P8 (3, 76.45)
  point P7 (3, 43.55)
  point P9 (3, 43.55)
  point P10 (3, 60)
  point P11 (5, 60)
  point P12 (3, 43.55)
  point P14 (3, 76.45)
  point P15 (3, 92.5)
  point P16 (3, 92.5)
  point P13 (3, 27.5)
  point P17 (3, 27.5)
  point P5 (5, 96.75)
  point P18 (5, 96.75)
  point P4 (5, 23.25)
  point P21 (5, 23.25)
  point P22 (-0.7, 23.25)
  point P23 (-0.7, 96.75)
  point P25 (37.3, 37.5)
  point P26 (37.3, 37.5)
  point P24 (37.3, 82.5)
  point P27 (37.3, 82.5)
  point P28 (3, 27.5)
  point P29 (37.3, 27.5)
  point P30 (3, 92.5)
  point P31 (37.3, 92.5)
  point P32 (-0.7, 73.95)
  point P35 (-0.7, 46.05)
  point P19 (41.3, 96.75)
  point P38 (31.8, 89.5)
  point P39 (18.3, 89.5)
  coincident P6 P8
  coincident P7 P9
  vertical L5
  midpoint L5 P10
  midpoint L3 P11
  horizontal L6
  equal C1 C2
  coincident P7 P12
  parallel L5 L7
  coincident P6 P14
  parallel L5 L8
  equal L7 L8
  coincident P15 P16
  coincident P13 P17
  equal C3 C4
  coincident P5 P18
  perpendicular L3 L9
  perpendicular L4 L10
  perpendicular L10 L11
  coincident P4 P21
  coincident L2 P22
  coincident L4 P23
  perpendicular L4 L12
  coincident P25 P26
  coincident P24 P27
  vertical L13
  equal C5 C6
  equal C3 C5
  coincident P17 P28
  horizontal L14
  coincident L13 P29
  coincident P16 P30
  perpendicular L8 L15
  coincident L13 P31
  coincident L12 P32
  perpendicular L12 L16
  perpendicular L16 L17
  coincident L12 P35
  perpendicular L12 L18
  horizontal L19
  vertical L20
  horizontal L21
  vertical L22
  dimension "d2729" distance P6 P7 = 32.9
  dimension "d2730" distance L1 P10 = 8
  dimension "d2731" diameter C1 = 1.7
  dimension "d2732" distance P13 P15 = 65
  dimension "d2733" diameter C3 = 3.5
  dimension "d2742" distance L5 L12 = 3.7
  dimension "d2764" distance P19 L12 = 42
  dimension "d2765" distance L10 L13 = 4
  dimension "d2766" distance L11 P25 = 14.25
  dimension "d2768" distance P26 P27 = 45
  dimension "d2769" distance P25 P29 = 10 (= "d2770")
  dimension "d2770" distance P24 P31 = 10
  dimension "d2779" distance P7 L18 = 2.5
  dimension "d2780" distance P6 L16 = 2.5
  dimension "d2781" distance P6 L17 = 3
  dimension "d2782" distance P31 L19 = 2
  dimension "d2783" distance P31 L21 = 3
  dimension "d2784" distance P38 P39 = 13.5
  dimension "d2785" distance P31 L20 = 5.5
extrude "Extrude255" add sketch "PCB Mount" profile of L3 C1 C2 C3 C4 L9 L10 L11 C5 C6 against normal blind 8
extrude "Extrude256" cut sketch "PCB Mount" profile of L3 C1 C2 C3 C4 against normal blind 9
extrude "Extrude259" cut sketch "PCB Mount" profile of L19 L20 L21 L22 against normal blind 3
extrude "Extrude257" add sketch "PCB Mount" profile of L2 L3 L4 C1 C2 C3 C4 L9 L10 L11 L12 C5 C6 L16 L17 L18 L19 L20 L21 L22 along normal blind 0.5
chamfer "Chamfer43" distance 0.5
chamfer "Chamfer44" distance 0.5
extrude "Extrude258" cut of existing geometry to an object
chamfer "Chamfer45" distance 1.1
component_insert "Component Insert80"
joint "Assemble81" alignAngle 0 alignOffsetX 0 alignOffsetY 0 alignOffsetZ 0
component_insert "Component Insert81"
joint "Assemble82" alignAngle 0 alignOffsetX 0 alignOffsetY 0 alignOffsetZ 0
component_insert "Component Insert82"
joint "Assemble83" alignAngle 0 alignOffsetX 0 alignOffsetY 0 alignOffsetZ 0
component_insert "Component Insert83"
joint "Assemble84" alignAngle 0 alignOffsetX 0 alignOffsetY 0 alignOffsetZ 0
component_insert "Component Insert84"
joint "Assemble85" alignAngle 0 alignOffsetX 0 alignOffsetY 0 alignOffsetZ 0
component_insert "Component Insert85"
joint "Assemble86" alignAngle 0 alignOffsetX 0 alignOffsetY 0 alignOffsetZ 0
component_insert "Component Insert92"
joint "Assemble93" alignAngle 0 alignOffsetX 0 alignOffsetY 0 alignOffsetZ 0
component_insert "Component Insert86"
joint "Assemble87" alignAngle 0 alignOffsetX 0 alignOffsetY 0 alignOffsetZ 0
component_insert "Component Insert87"
joint "Assemble88" alignAngle 0 alignOffsetX 0 alignOffsetY 0 alignOffsetZ 0
component_insert "Component Insert79"
joint "Assemble80" alignAngle 90 alignOffsetX 0 alignOffsetY 0 alignOffsetZ 0
component_insert "Component Insert88"
joint "Assemble89" alignAngle 90 alignOffsetX 0 alignOffsetY 0 alignOffsetZ 0
component_insert "Component Insert89"
joint "Assemble90" alignAngle 90 alignOffsetX 0 alignOffsetY 0 alignOffsetZ 0
component_insert "Component Insert90"
joint "Assemble91" alignAngle 90 alignOffsetX 0 alignOffsetY 0 alignOffsetZ 0
component_insert "Component Insert91"
joint "Assemble92" alignAngle 90 alignOffsetX 0 alignOffsetY 0 alignOffsetZ 0
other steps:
joint_origin "JointOrigin81"
joint_origin "JointOrigin93"
joint_origin "JointOrigin94"
joint_origin "JointOrigin95"
joint_origin "JointOrigin96"
joint_origin "JointOrigin97"
joint_origin "JointOrigin98"
joint_origin "JointOrigin99"
joint_origin "JointOrigin100"
joint_origin "JointOrigin101"
named bodies: "Hotplate Cam Template"

design "TE-10p-2p5-blade_1123684-07"
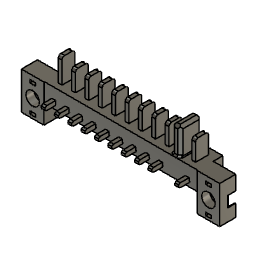
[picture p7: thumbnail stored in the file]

design "M3x25-FHCS"
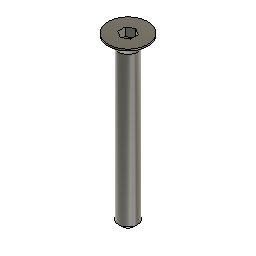
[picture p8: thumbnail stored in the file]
sketch "Sketch1" plane through (0, 0, 0) normal (0, 1, 0) x axis (1, 0, 0)
  line L1 (0, 25) -> (0, 0)
  line L2 (0.95, 25) -> (0, 25)
  line L3 (1.45, 24.5) -> (0.95, 25)
  line L4 (1.45, 1.8) -> (1.45, 24.5)
  line L5 (3, 0.25) -> (1.45, 1.8)
  line L6 (3, 0) -> (3, 0.25)
  line L7 (0, 0) -> (3, 0)
  point P1 (0, 0)
  point P2 (0, 0)
  point P9 (0, 0)
  point P3 (0, 25)
  point P4 (0.95, 25)
  point P8 (3, 0)
  point P7 (3, 0.25)
  coincident P1 P2
  vertical L1
  perpendicular L1 L2
  perpendicular L2 L4
  parallel L3 L5
  parallel L4 L6
  perpendicular L6 L7
  coincident P1 P9
  dimension "d1" distance P3 L4 = 1.45 (= "( 2.9 / 2 ) * 1 mm")
  dimension "d3" angle L2 L3 = 45
  dimension "d5" distance P4 L4 = 0.5
  dimension "d6" distance P2 P3 = 25
  dimension "d7" distance P8 P9 = 3 (= "( 6 / 2 ) * 1 mm")
  dimension "d9" distance P7 P8 = 0.25
revolve "Revolve1" sketch "Sketch1" AlongAngle 360
sketch "Sketch2" plane through (0, 0, 0) normal (0, 0, 1) x axis (-1, 0, 0)
  line L1 (0, -1.1547) -> (-1, -0.5774)
  line L2 (1, -0.5774) -> (0, -1.1547)
  line L3 (1, 0.5774) -> (1, -0.5774)
  line L4 (0, 1.1547) -> (1, 0.5774)
  line L5 (-1, 0.5774) -> (0, 1.1547)
  line L6 (-1, -0.5774) -> (-1, 0.5774)
  circle C1 centre (0, 0) radius 3
  point P1 (0, 0)
  point P9 (0, 0)
  coincident P1 P9
  vertical L6
  dimension "d12" distance L3 L6 = 2
extrude "Extrude1" cut sketch "Sketch2" profile of L1 L2 L3 L4 L5 L6 against normal blind 1.26

design "M3x20-SHCS"
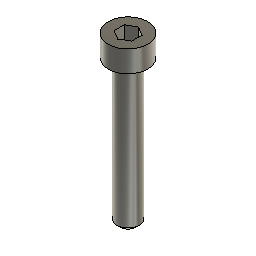
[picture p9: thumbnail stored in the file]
sketch "Sketch1" plane through (0, 0, 0) normal (0, 1, 0) x axis (1, 0, 0)
  line L1 (0, 20) -> (0, -3)
  line L2 (1.05, 20) -> (0, 20)
  line L3 (1.55, 19.5) -> (1.05, 20)
  line L4 (1.55, 0) -> (1.55, 19.5)
  line L5 (2.75, 0) -> (1.55, 0)
  line L6 (2.75, -3) -> (2.75, 0)
  line L7 (0, -3) -> (2.75, -3)
  point P1 (0, 0)
  point P4 (1.05, 20)
  point P5 (1.55, 19.5)
  point P3 (0, 20)
  point P7 (2.75, 0)
  point P8 (2.75, -3)
  point P2 (0, -3)
  vertical L1
  perpendicular L1 L2
  perpendicular L2 L4
  perpendicular L4 L5
  perpendicular L5 L6
  horizontal L7
  coincident P1 L1
  coincident P1 L5
  dimension "d1" distance P1 L2 = 20
  dimension "d2" angle L2 L3 = 45
  dimension "d3" distance P4 P5 = 0.5
  dimension "d4" distance P3 L4 = 1.55 (= "( 3.1 / 2 ) * 1 mm")
  dimension "d5" distance P7 P8 = 3
  dimension "d6" distance P2 P8 = 2.75 (= "( 5.5 / 2 ) * 1 mm")
revolve "Revolve1" sketch "Sketch1" AlongAngle 360
sketch "Sketch2" plane through (0, 0, 3) normal (0, 0, 1) x axis (-1, 0, 0)
  line L1 (0, -1.4434) -> (-1.25, -0.7217)
  line L2 (1.25, -0.7217) -> (0, -1.4434)
  line L3 (1.25, 0.7217) -> (1.25, -0.7217)
  line L4 (0, 1.4434) -> (1.25, 0.7217)
  line L5 (-1.25, 0.7217) -> (0, 1.4434)
  line L6 (-1.25, -0.7217) -> (-1.25, 0.7217)
  circle C1 centre (0, 0) radius 2.75
  point P1 (0, 0)
  point P9 (0, 0)
  point P5 (1.25, -0.7217)
  coincident P1 P9
  vertical L6
  dimension "d8" distance P5 L6 = 2.5
extrude "Extrude1" cut sketch "Sketch2" profile of L1 L2 L3 L4 L5 L6 against normal blind 2

design "M4x14-BHCS"
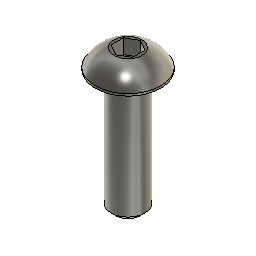
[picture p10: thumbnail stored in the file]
sketch "Sketch1" plane through (0, 0, 0) normal (0, 1, 0) x axis (1, 0, 0)
  line L1 (0, 14) -> (0, -2.2)
  line L2 (1.45, 14) -> (0, 14)
  line L3 (1.95, 13.5) -> (1.45, 14)
  line L4 (1.95, 0) -> (1.95, 13.5)
  line L5 (3.8, 0) -> (1.95, 0)
  line L6 (3.8, -0.25) -> (3.8, 0)
  line L7 (1.6, -2.2) -> (0, -2.2)
  arc A1 centre (0, 1.8212) radius 4.3278 clockwise from (3.8, -0.25) to (1.6, -2.2)
  point P1 (0, 0)
  point P10 (0, 1.8212)
  point P3 (0, 14)
  point P2 (0, -2.2)
  point P9 (1.6, -2.2)
  point P7 (3.8, 0)
  point P8 (3.8, -0.25)
  point P5 (1.95, 13.5)
  vertical L1
  perpendicular L1 L2
  perpendicular L2 L4
  perpendicular L4 L5
  perpendicular L5 L6
  perpendicular L1 L7
  coincident P1 L5
  coincident L1 P10
  coincident P1 L1
  dimension "d1" distance P1 P3 = 14
  dimension "d2" distance P1 P2 = 2.2
  dimension "d3" distance P2 P9 = 1.6
  dimension "d4" distance P7 P8 = 0.25
  dimension "d5" distance L1 P7 = 3.8 (= "( 7.6 / 2 ) * 1 mm")
  dimension "d6" distance P1 L4 = 1.95 (= "( 3.9 / 2 ) * 1 mm")
  dimension "d7" angle L2 L3 = 45
  dimension "d8" distance L2 P5 = 0.5
revolve "Revolve1" sketch "Sketch1" AlongAngle 360
sketch "Sketch2" plane through (0, 0, 2.2) normal (0, 0, 1) x axis (-1, 0, 0)
  line L1 (0, -1.4434) -> (-1.25, -0.7217)
  line L2 (1.25, -0.7217) -> (0, -1.4434)
  line L3 (1.25, 0.7217) -> (1.25, -0.7217)
  line L4 (0, 1.4434) -> (1.25, 0.7217)
  line L5 (-1.25, 0.7217) -> (0, 1.4434)
  line L6 (-1.25, -0.7217) -> (-1.25, 0.7217)
  circle C1 centre (0, 0) radius 1.6
  point P2 (0, 0)
  point P9 (0, 0)
  point P5 (1.25, -0.7217)
  coincident P2 P9
  vertical L3
  dimension "d10" distance P5 L6 = 2.5
extrude "Extrude1" cut sketch "Sketch2" profile of L1 L2 L3 L4 L5 L6 to an object offset 0.5

design "M3 Washer"
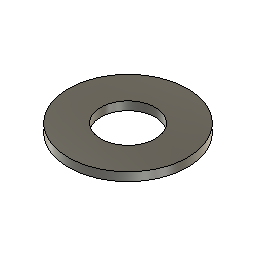
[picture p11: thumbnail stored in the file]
sketch "Sketch1" plane through (0, 0, 0) normal (0, 1, 0) x axis (1, 0, 0)
  line L1 (3.5, 0) -> (1.6, 0)
  line L2 (3.5, -0.5) -> (3.5, 0)
  line L3 (1.6, -0.5) -> (3.5, -0.5)
  line L4 (1.6, 0) -> (1.6, -0.5)
  point P1 (0, 0)
  point P2 (1.6, 0)
  point P5 (1.6, -0.5)
  horizontal L1
  vertical L2
  horizontal L3
  vertical L4
  coincident P1 L1
  dimension "d1" distance P2 P5 = 0.5
  dimension "d2" distance P1 L4 = 1.6 (= "( 3.2 / 2 ) * 1 mm")
  dimension "d3" distance P1 L2 = 3.5 (= "( 7 / 2 ) * 1 mm")
revolve "Revolve1" sketch "Sketch1" AlongAngle 360

design "3.2x4.5x4mm Unthreaded Spacer"
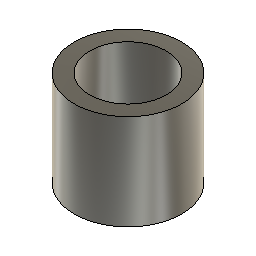
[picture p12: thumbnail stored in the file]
sketch "Sketch1" plane through (0, 0, 0) normal (0, 1, 0) x axis (1, 0, 0)
  line L1 (2.25, 0) -> (1.6, 0)
  line L2 (2.25, -4) -> (2.25, 0)
  line L3 (1.6, -4) -> (2.25, -4)
  line L4 (1.6, 0) -> (1.6, -4)
  point P1 (0, 0)
  point P3 (2.25, 0)
  point P4 (2.25, -4)
  horizontal L1
  vertical L2
  horizontal L3
  vertical L4
  coincident P1 L1
  dimension "d1" distance P1 L4 = 1.6 (= "( 3.2 / 2 ) * 1 mm")
  dimension "d2" distance P1 L2 = 2.25 (= "( 4.5 / 2 ) * 1 mm")
  dimension "d3" distance P3 P4 = 4
revolve "Revolve1" sketch "Sketch1" AlongAngle 360

design "M3x14-FHCS"
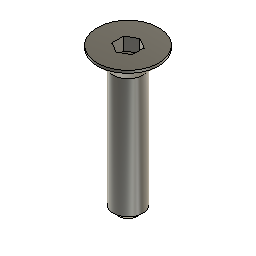
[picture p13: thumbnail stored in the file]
sketch "Sketch1" plane through (0, 0, 0) normal (0, 1, 0) x axis (1, 0, 0)
  line L1 (0, 14) -> (0, 0)
  line L2 (0.95, 14) -> (0, 14)
  line L3 (1.45, 13.5) -> (0.95, 14)
  line L4 (1.45, 1.8) -> (1.45, 13.5)
  line L5 (3, 0.25) -> (1.45, 1.8)
  line L6 (3, 0) -> (3, 0.25)
  line L7 (0, 0) -> (3, 0)
  point P1 (0, 0)
  point P2 (0, 0)
  point P9 (0, 0)
  point P3 (0, 14)
  point P4 (0.95, 14)
  point P8 (3, 0)
  point P7 (3, 0.25)
  coincident P1 P2
  vertical L1
  perpendicular L1 L2
  perpendicular L2 L4
  parallel L3 L5
  parallel L4 L6
  perpendicular L6 L7
  coincident P1 P9
  dimension "d1" distance P3 L4 = 1.45 (= "( 2.9 / 2 ) * 1 mm")
  dimension "d3" angle L2 L3 = 45
  dimension "d5" distance P4 L4 = 0.5
  dimension "d6" distance P2 P3 = 14
  dimension "d7" distance P8 P9 = 3 (= "( 6 / 2 ) * 1 mm")
  dimension "d9" distance P7 P8 = 0.25
revolve "Revolve1" sketch "Sketch1" AlongAngle 360
sketch "Sketch2" plane through (0, 0, 0) normal (0, 0, 1) x axis (-1, 0, 0)
  line L1 (0, -1.1547) -> (-1, -0.5774)
  line L2 (1, -0.5774) -> (0, -1.1547)
  line L3 (1, 0.5774) -> (1, -0.5774)
  line L4 (0, 1.1547) -> (1, 0.5774)
  line L5 (-1, 0.5774) -> (0, 1.1547)
  line L6 (-1, -0.5774) -> (-1, 0.5774)
  circle C1 centre (0, 0) radius 3
  point P1 (0, 0)
  point P9 (0, 0)
  coincident P1 P9
  vertical L6
  dimension "d12" distance L3 L6 = 2
extrude "Extrude1" cut sketch "Sketch2" profile of L1 L2 L3 L4 L5 L6 against normal blind 1.26

design "PCB Blade Head" references "TE-10p-2p5-socket_1674231"
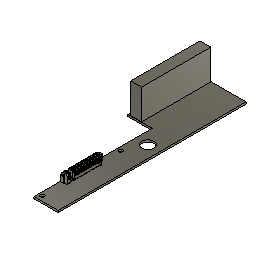
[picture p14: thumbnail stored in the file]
